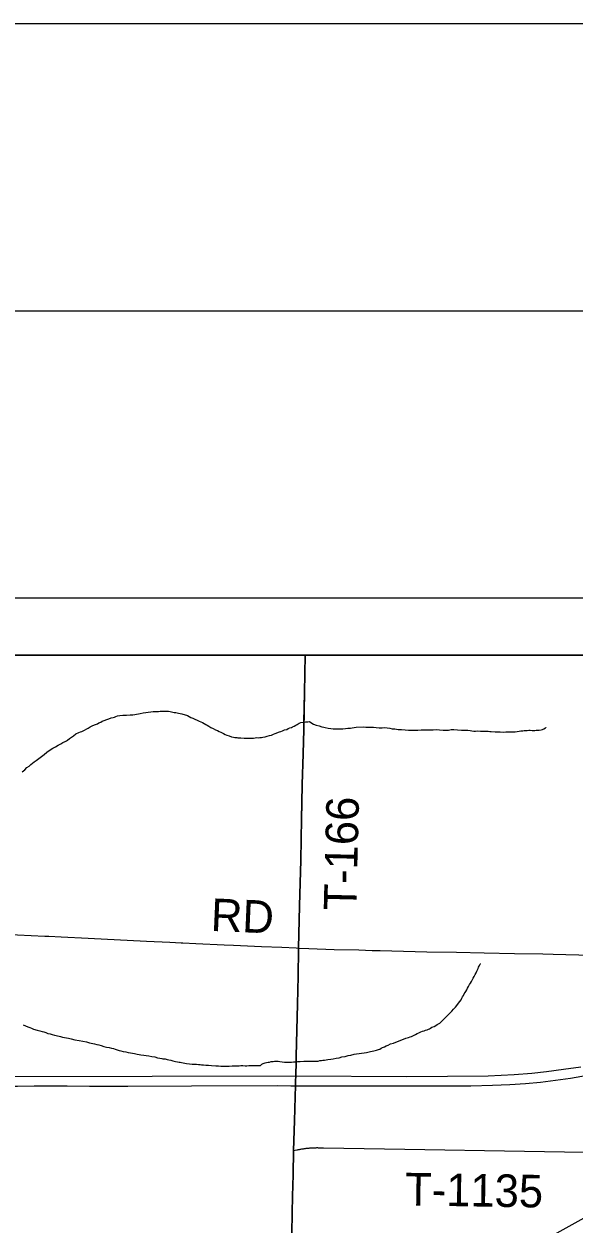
# Model space of a CAD drawing. Extents: x 0 to 34, y 0 to 22.
# Drawn here: x 28.42 to 29.379, y 19.908 to 22 of the extents above; entities that cross this region are included whole.
import ezdxf

# ---------------------------------------------------------------- set-up
doc = ezdxf.new("R2010")
doc.units = 0
for name, color, linetype in [('GM_X_City_Street', 7, 'Continuous'), ('GM_X_County_Road', 7, 'Continuous'), ('GM_X_County_Road_Text', 7, 'Continuous'), ('GM_X_Minor_River', 7, 'Continuous'), ('GM_X_Rail_Line', 7, 'Continuous'), ('GM_X_Township_Road', 7, 'Continuous'), ('GM_X_Township_Road_Text', 7, 'Continuous'), ('GM_X_US_Route', 7, 'Continuous'), ('SH_Border', 7, 'Continuous'), ('SH_Cut_Line', 7, 'Continuous'), ('SH_Data', 7, 'Continuous')]:
    doc.layers.add(name, color=color, linetype=linetype)

msp = doc.modelspace()

# ---------------------------------------------------------------- linework, layer by layer
at = {"layer": 'GM_X_City_Street'}
msp.add_lwpolyline([(28.8904, 20.0361), (28.8959, 20.0373), (28.8971, 20.0376), (28.8983, 20.0379), (28.8995, 20.0381), (28.9007, 20.0384), (28.9019, 20.0386), (28.9032, 20.0388), (28.9044, 20.039), (28.9056, 20.0392), (28.9062, 20.0393), (28.9074, 20.0395), (28.9086, 20.0397), (28.9099, 20.0399), (28.9111, 20.0401), (28.9123, 20.0402), (28.9135, 20.0403), (28.9148, 20.0405), (28.916, 20.0406), (28.9172, 20.0407), (28.9185, 20.0408), (28.9197, 20.0409), (28.9209, 20.041), (28.9222, 20.0411), (28.9228, 20.0411), (28.924, 20.0412), (28.9246, 20.0412), (28.9259, 20.0413), (28.9265, 20.0413), (28.9277, 20.0413), (28.929, 20.0413), (28.9296, 20.0413), (28.9308, 20.0414), (28.932, 20.0414), (28.9333, 20.0413), (28.9339, 20.0413), (28.9351, 20.0413), (28.9364, 20.0413), (28.9376, 20.0412), (28.9382, 20.0412), (28.9395, 20.0412), (28.9401, 20.0411), (28.9413, 20.0411), (28.9425, 20.041), (29.0843, 20.0386), (29.502, 20.0316)], dxfattribs=at)
at = {"layer": 'GM_X_County_Road'}
for points in [[(29.3428, 20.3785), (29.41, 20.3768), (29.4264, 20.3781), (29.4402, 20.3804), (29.4531, 20.3834), (29.4669, 20.3876), (29.4833, 20.3942), (29.4938, 20.4005), (29.5076, 20.409), (29.5198, 20.4179), (29.5323, 20.4291), (29.5454, 20.4432), (29.6523, 20.5721)], [(28.2557, 20.4201), (28.3015, 20.4177), (28.3605, 20.4149), (28.4562, 20.4101), (28.4633, 20.4098)], [(28.4633, 20.4098), (28.4847, 20.4089), (28.5319, 20.4065), (28.6338, 20.4015), (28.6742, 20.3993), (28.694, 20.3983), (28.6971, 20.3982)], [(28.6971, 20.3982), (28.7195, 20.3971), (28.7694, 20.3949)], [(28.7694, 20.3949), (28.7853, 20.3941), (28.8344, 20.3919), (28.8698, 20.3906), (28.8947, 20.3895), (28.8993, 20.3893)], [(28.8993, 20.3893), (28.917, 20.3887), (28.9611, 20.3869), (29.004, 20.3859), (29.0276, 20.3852), (29.0415, 20.3848)], [(29.0415, 20.3848), (29.1227, 20.3829), (29.1743, 20.3818), (29.2228, 20.3809), (29.2757, 20.3798), (29.3248, 20.3789), (29.3428, 20.3785)]]:
    msp.add_lwpolyline(points, dxfattribs=at)
at = {"layer": 'GM_X_Minor_River'}
for points in [[(28.4169, 20.6963), (28.4212, 20.7), (28.4251, 20.7037), (28.429, 20.7062), (28.4321, 20.7092), (28.4348, 20.7114), (28.4379, 20.7136), (28.441, 20.7162), (28.455, 20.7268), (28.4601, 20.7308), (28.4655, 20.7345), (28.4705, 20.7374), (28.4752, 20.7403), (28.4798, 20.7428), (28.484, 20.7453), (28.4879, 20.7475), (28.4918, 20.7493), (28.4941, 20.7507), (28.496, 20.7514), (28.4995, 20.7548), (28.503, 20.7569), (28.5065, 20.7591), (28.5104, 20.7624), (28.5158, 20.7649), (28.5188, 20.7664), (28.5208, 20.7667), (28.5231, 20.7681), (28.5319, 20.7728), (28.5354, 20.7746), (28.5401, 20.7772), (28.5447, 20.7789), (28.5485, 20.7803), (28.5508, 20.7818), (28.5539, 20.7832), (28.5566, 20.7847), (28.5601, 20.7861), (28.5643, 20.7875), (28.5681, 20.7889), (28.572, 20.7903), (28.5754, 20.7913), (28.5777, 20.792)], [(28.5777, 20.792), (28.58, 20.7931), (28.5831, 20.7942), (28.5873, 20.7948), (28.5922, 20.795), (28.5991, 20.7952), (28.6052, 20.7958), (28.6101, 20.796), (28.6132, 20.7963), (28.6162, 20.797), (28.6197, 20.7973), (28.6227, 20.798), (28.6277, 20.799), (28.6323, 20.7996), (28.6368, 20.8002), (28.641, 20.8012), (28.6452, 20.8015), (28.6486, 20.8014), (28.6517, 20.8017), (28.6547, 20.8016), (28.6574, 20.8019), (28.6608, 20.8022), (28.6635, 20.8021), (28.6661, 20.802), (28.6699, 20.8019), (28.6722, 20.8019), (28.6748, 20.8014), (28.6775, 20.8009), (28.6798, 20.8005), (28.682, 20.8001), (28.6847, 20.8), (28.6873, 20.7991), (28.6896, 20.7987), (28.6922, 20.7982), (28.6956, 20.7974), (28.705, 20.7945), (28.708, 20.7928), (28.711, 20.7912), (28.7144, 20.79), (28.7178, 20.788), (28.7219, 20.7864), (28.7256, 20.7847), (28.7286, 20.7835), (28.7316, 20.7823), (28.7343, 20.7807), (28.7372, 20.7791), (28.7395, 20.7775), (28.7425, 20.7759), (28.7458, 20.7739), (28.7499, 20.7719), (28.7541, 20.7699), (28.7578, 20.7682), (28.7604, 20.767), (28.7631, 20.7658), (28.7657, 20.7642), (28.7679, 20.763), (28.7709, 20.7618), (28.7739, 20.7602), (28.7777, 20.7589), (28.7818, 20.7577), (28.7856, 20.7568), (28.7875, 20.7563), (28.7894, 20.7563), (28.7913, 20.7562), (28.7932, 20.7558), (28.7954, 20.7557), (28.7981, 20.7557), (28.8038, 20.7551), (28.8079, 20.755), (28.8129, 20.7549), (28.8167, 20.7551), (28.8201, 20.7554), (28.8232, 20.7557), (28.8258, 20.756), (28.8285, 20.7559), (28.8312, 20.7562), (28.8342, 20.7565), (28.8369, 20.7568), (28.8407, 20.7575), (28.8441, 20.7585), (28.848, 20.7595), (28.8518, 20.7606), (28.8553, 20.762), (28.8583, 20.763), (28.8656, 20.7659), (28.8683, 20.7669), (28.871, 20.768), (28.8745, 20.7694), (28.8787, 20.7704), (28.881, 20.7719), (28.8837, 20.773), (28.8864, 20.774), (28.8883, 20.7747), (28.8914, 20.7762), (28.8941, 20.778), (28.8964, 20.7791), (28.8999, 20.7812), (28.9029, 20.7823), (28.9075, 20.7829), (28.911, 20.7836), (28.9151, 20.7838)], [(28.9151, 20.7838), (28.9182, 20.7841), (28.9204, 20.7822), (28.9249, 20.7798), (28.9298, 20.7777), (28.9351, 20.7764), (28.9396, 20.7751), (28.943, 20.7743), (28.9456, 20.7735), (28.9505, 20.7726), (28.9551, 20.772), (28.9596, 20.7715), (28.9649, 20.7714), (28.9706, 20.7712), (28.9763, 20.7714), (28.9809, 20.7717), (28.9851, 20.7723), (28.9893, 20.7726), (28.9923, 20.7733), (28.9958, 20.7739), (28.9996, 20.7742), (29.0125, 20.7746), (29.0163, 20.7745), (29.0201, 20.7744), (29.0243, 20.7742), (29.0296, 20.7741), (29.0345, 20.7739), (29.0398, 20.7734), (29.0447, 20.7733), (29.0493, 20.7735), (29.0538, 20.773), (29.058, 20.7725), (29.0622, 20.7716), (29.0667, 20.7711), (29.0728, 20.7702), (29.0788, 20.77), (29.0849, 20.7694), (29.0906, 20.7693), (29.0963, 20.7691), (29.1016, 20.769), (29.1069, 20.7688), (29.1126, 20.7694), (29.121, 20.7695), (29.1274, 20.7697), (29.1339, 20.7699), (29.1388, 20.7702), (29.1449, 20.7696), (29.151, 20.7691), (29.1567, 20.7689), (29.1605, 20.7692), (29.1654, 20.7702), (29.1696, 20.77), (29.1761, 20.7695), (29.1829, 20.7693), (29.189, 20.7691), (29.1943, 20.7689), (29.1984, 20.7684), (29.2011, 20.768), (29.2049, 20.7675), (29.2075, 20.7674), (29.2106, 20.7677), (29.2163, 20.7676), (29.2216, 20.7674), (29.2261, 20.7673), (29.2295, 20.7672), (29.2326, 20.7667), (29.2348, 20.7666), (29.242, 20.766), (29.2458, 20.7663), (29.2504, 20.7662), (29.2565, 20.7656), (29.2603, 20.7659), (29.2641, 20.7662), (29.2683, 20.7661), (29.2732, 20.7663), (29.277, 20.7662), (29.2801, 20.7669), (29.2835, 20.7671), (29.2869, 20.7678), (29.29, 20.7681), (29.2926, 20.7684), (29.2953, 20.7683), (29.298, 20.7686), (29.3006, 20.7689), (29.3029, 20.7689), (29.3067, 20.7687), (29.3086, 20.7687), (29.3109, 20.7686), (29.3132, 20.7689), (29.3154, 20.7689), (29.3185, 20.7692), (29.3219, 20.7698), (29.3246, 20.7705), (29.3269, 20.7716), (29.3296, 20.7734), (29.3304, 20.7738), (29.3304, 20.7734)], [(29.0455, 20.2157), (29.0486, 20.2171), (29.0517, 20.2186), (29.0555, 20.22), (29.0594, 20.2221), (29.0647, 20.2235), (29.0686, 20.2253), (29.0732, 20.227), (29.0774, 20.2288), (29.082, 20.2306), (29.0862, 20.232), (29.0905, 20.2334), (29.0935, 20.2344), (29.0958, 20.2351), (29.0981, 20.2362), (29.1004, 20.2373), (29.1028, 20.2384), (29.1059, 20.2402), (29.1089, 20.2416), (29.112, 20.243), (29.1151, 20.2441), (29.1178, 20.2451), (29.1205, 20.2462), (29.1231, 20.2469), (29.1255, 20.248), (29.1274, 20.2487), (29.1293, 20.2498), (29.1316, 20.2512), (29.1355, 20.2526), (29.1382, 20.2541), (29.1409, 20.2559), (29.1432, 20.257), (29.1451, 20.2584), (29.1482, 20.261), (29.1502, 20.2628), (29.1522, 20.2651), (29.1549, 20.2676), (29.158, 20.271), (29.1627, 20.2758), (29.1663, 20.2795), (29.1694, 20.2828), (29.1725, 20.2865), (29.1804, 20.2962), (29.1824, 20.2991), (29.1836, 20.3018), (29.1852, 20.3044), (29.1864, 20.3066), (29.188, 20.3096), (29.1896, 20.3115), (29.1908, 20.3137), (29.1924, 20.3163), (29.1936, 20.3193), (29.1952, 20.3223), (29.1972, 20.3257), (29.1988, 20.3283), (29.2004, 20.3309), (29.202, 20.3335), (29.2036, 20.3365), (29.2052, 20.3395), (29.2069, 20.3433), (29.2085, 20.3463), (29.2097, 20.3489), (29.2109, 20.3512), (29.2121, 20.3538), (29.2129, 20.356), (29.2138, 20.3579), (29.2154, 20.3605), (29.2162, 20.362), (29.2158, 20.362)], [(28.4184, 20.2554), (28.4225, 20.2534), (28.4266, 20.2518), (28.4304, 20.2509), (28.433, 20.2497), (28.4368, 20.2477), (28.4428, 20.2464), (28.4477, 20.2451), (28.4515, 20.2439), (28.4549, 20.243), (28.4583, 20.2418), (28.4616, 20.2405), (28.4654, 20.2397), (28.4692, 20.2384), (28.473, 20.2375), (28.476, 20.2367), (28.4786, 20.2362), (28.4816, 20.2358), (28.4839, 20.2349), (28.4869, 20.2341), (28.4975, 20.2319), (28.5024, 20.231), (28.5088, 20.2293), (28.516, 20.2279), (28.5228, 20.227), (28.5288, 20.2257), (28.5345, 20.224), (28.5401, 20.2231), (28.5428, 20.2222), (28.5469, 20.2213), (28.5507, 20.2205), (28.5548, 20.2192), (28.5594, 20.2179), (28.5639, 20.2167), (28.5688, 20.2158), (28.5729, 20.2149), (28.5763, 20.214), (28.579, 20.2132), (28.5827, 20.2119), (28.5861, 20.2107), (28.5891, 20.2099), (28.5929, 20.209), (28.5974, 20.2081), (28.602, 20.2072), (28.6058, 20.2067), (28.6092, 20.2062), (28.6129, 20.2054), (28.6175, 20.2045), (28.6209, 20.204), (28.6239, 20.2032), (28.6288, 20.2026), (28.633, 20.2018)], [(28.633, 20.2018), (28.6375, 20.2012), (28.6428, 20.2003), (28.6481, 20.1994), (28.653, 20.1981), (28.6571, 20.1976), (28.6602, 20.1968), (28.662, 20.1964), (28.6639, 20.1963), (28.6662, 20.1959), (28.6696, 20.195), (28.6726, 20.1945), (28.676, 20.1937), (28.6798, 20.1924), (28.6843, 20.1915), (28.6877, 20.1911), (28.6907, 20.1906), (28.6926, 20.1902), (28.6945, 20.1897), (28.7032, 20.1879), (28.7085, 20.1874), (28.7134, 20.1869), (28.718, 20.1868), (28.721, 20.1867), (28.7244, 20.1862), (28.7275, 20.1861), (28.7297, 20.1857), (28.7331, 20.1856), (28.7373, 20.1851), (28.7419, 20.1849), (28.7472, 20.1844), (28.7544, 20.1842), (28.7593, 20.1837), (28.7635, 20.1835), (28.7673, 20.1834), (28.7718, 20.1833), (28.7779, 20.1835), (28.7832, 20.1837), (28.7874, 20.184), (28.7916, 20.1839), (28.7954, 20.1841), (28.7984, 20.1844), (28.8015, 20.1843), (28.8057, 20.1842), (28.8087, 20.1841), (28.8121, 20.1844), (28.8167, 20.1847), (28.8228, 20.1845), (28.8277, 20.1844), (28.8304, 20.1847), (28.8326, 20.1846), (28.8346, 20.1868), (28.8373, 20.1879), (28.8407, 20.1889), (28.843, 20.1896), (28.8457, 20.1903), (28.848, 20.1906), (28.8514, 20.1913), (28.8545, 20.1916), (28.8572, 20.1919), (28.8591, 20.1922), (28.8632, 20.1921), (28.8663, 20.1916), (28.8701, 20.1911), (28.8742, 20.1906), (28.8788, 20.1901), (28.8829, 20.1904), (28.8867, 20.1906), (28.8902, 20.1909), (28.8932, 20.1912), (28.897, 20.1915), (28.9016, 20.1917), (28.9084, 20.1919), (28.9138, 20.1921), (28.9198, 20.192), (28.9255, 20.1922), (28.9301, 20.192), (28.9331, 20.1923), (28.9362, 20.193), (28.9389, 20.1933), (28.9415, 20.1936), (28.9442, 20.1939), (28.9469, 20.1942), (28.9503, 20.1949), (28.9553, 20.1955), (28.9595, 20.1961), (28.9648, 20.1971), (28.9698, 20.1981), (28.9744, 20.1995), (28.9801, 20.2005), (28.9855, 20.2018), (28.9904, 20.2028), (28.9958, 20.2042), (29.0175, 20.2074), (29.0244, 20.2087), (29.0301, 20.21), (29.0347, 20.2111), (29.0382, 20.2125), (29.0405, 20.2132), (29.0428, 20.2146), (29.0455, 20.2157)]]:
    msp.add_lwpolyline(points, dxfattribs=at)
at = {"layer": 'GM_X_Rail_Line'}
msp.add_lwpolyline([(29.1835, 19.8007), (29.9023, 20.1997)], dxfattribs=at)
at = {"layer": 'GM_X_Township_Road'}
for p, q in [((28.9104, 20.8873), (28.9106, 20.9)), ((28.9082, 20.7747), (28.9084, 20.7837)), ((28.8973, 20.2911), (28.8977, 20.3109))]:
    msp.add_line(p, q, dxfattribs=at)
for points in [[(28.887, 19.8915), (28.8877, 19.9276), (28.8884, 19.9568), (28.8895, 19.9942), (28.8902, 20.0366), (28.8916, 20.0879), (28.893, 20.1302), (28.8935, 20.1497), (28.8937, 20.1571), (28.894, 20.1668), (28.8946, 20.1915), (28.8949, 20.2008), (28.8952, 20.2232), (28.8965, 20.2686), (28.8971, 20.2916), (28.898, 20.3401), (28.8989, 20.3865), (28.899, 20.3899), (28.9007, 20.4627), (28.9028, 20.5422), (28.9041, 20.6143), (28.9049, 20.6429), (28.9055, 20.6746), (28.9069, 20.728), (28.9079, 20.7703), (28.9091, 20.8349), (28.9104, 20.9), (23.5167, 20.9)], [(30.3167, 20.9), (28.9104, 20.9), (28.9091, 20.8349), (28.9079, 20.7703), (28.9069, 20.728), (28.9055, 20.6746), (28.9049, 20.6429), (28.9041, 20.6143), (28.9028, 20.5422), (28.9007, 20.4627), (28.899, 20.3899), (28.8989, 20.3865), (28.898, 20.3401), (28.8971, 20.2916), (28.8965, 20.2686), (28.8952, 20.2232), (28.8949, 20.2008), (28.8946, 20.1915), (28.894, 20.1668), (28.8937, 20.1571), (28.8935, 20.1497), (28.893, 20.1302), (28.8916, 20.0879), (28.8902, 20.0366), (28.8895, 19.9942), (28.8884, 19.9568), (28.8877, 19.9276), (28.887, 19.8915)], [(28.9084, 20.7837), (28.9093, 20.8344), (28.9104, 20.8873)], [(28.8993, 20.3893), (28.901, 20.4621), (28.903, 20.5417), (28.9044, 20.6138), (28.9052, 20.6423), (28.9058, 20.6741), (28.9072, 20.7275), (28.9081, 20.7698), (28.9082, 20.7747)], [(28.8977, 20.3109), (28.8982, 20.3395), (28.8992, 20.3859), (28.8993, 20.3893)], [(28.8938, 20.1491), (28.894, 20.1565), (28.8942, 20.1663), (28.8948, 20.1909), (28.8951, 20.2002), (28.8955, 20.2226), (28.8967, 20.2681), (28.8973, 20.2911)], [(28.8904, 20.0361), (28.8918, 20.0874), (28.8932, 20.1296), (28.8938, 20.1491)], [(28.8823, 19.6941), (28.8823, 19.6952), (28.883, 19.7157), (28.8835, 19.7399), (28.8842, 19.7642), (28.885, 19.8002), (28.8853, 19.8238), (28.886, 19.8487), (28.8868, 19.8761), (28.8872, 19.891), (28.8879, 19.927), (28.8887, 19.9562), (28.8897, 19.9936), (28.8904, 20.0361)]]:
    msp.add_lwpolyline(points, dxfattribs=at)
at = {"layer": 'GM_X_US_Route'}
for points in [[(29.0865, 20.149), (29.0875, 20.149), (29.1993, 20.1493), (29.2371, 20.1501), (29.2676, 20.1514), (29.2948, 20.1532), (29.3208, 20.1557), (29.3473, 20.1589), (29.3731, 20.1627), (29.4031, 20.1679), (29.4305, 20.1734), (29.4614, 20.1804), (29.4891, 20.1874), (29.5035, 20.1912), (29.5044, 20.1915)], [(28.393, 20.1652), (28.8942, 20.1663), (29.0877, 20.1653), (29.2299, 20.1663), (29.2752, 20.1687), (29.3061, 20.1713), (29.3314, 20.1739), (29.361, 20.1779), (29.3916, 20.1825)], [(28.3922, 20.1488), (28.3932, 20.1488), (28.4085, 20.1488), (28.4377, 20.149), (28.4955, 20.1493), (28.5345, 20.1488), (28.6014, 20.1488), (28.712, 20.1491), (28.8624, 20.1494), (28.8856, 20.1492), (28.8938, 20.1491)], [(28.8938, 20.1491), (29.0389, 20.1493), (29.0865, 20.149)]]:
    msp.add_lwpolyline(points, dxfattribs=at)
at = {"layer": 'SH_Border'}
msp.add_lwpolyline([(1.5, 21.5), (33.5, 21.5), (33.5, 0.5), (1.5, 0.5)], close=True, dxfattribs=at)
at = {"layer": 'SH_Cut_Line'}
msp.add_lwpolyline([(0, 0), (34, 0), (34, 22), (0, 22)], close=True, dxfattribs=at)
at = {"layer": 'SH_Data'}
for points in [[(23.4167, 21), (30.4167, 21), (30.4167, 14), (23.4167, 14)], [(23.5167, 20.9), (30.3167, 20.9), (30.3167, 14.1), (23.5167, 14.1)]]:
    msp.add_lwpolyline(points, close=True, dxfattribs=at)

# ---------------------------------------------------------------- texts
at = {"layer": 'GM_X_County_Road_Text'}
msp.add_text('RD', height=0.05682, rotation=357.554, dxfattribs=at).set_placement((28.7451, 20.4192))
at = {"layer": 'GM_X_Township_Road_Text'}
for s, rotation, p in [('T-166', 88.5955, (28.9996, 20.4541)), ('T-1135', 359.0643, (29.0844, 19.9408))]:
    msp.add_text(s, height=0.05682, rotation=rotation, dxfattribs=at).set_placement(p)

doc.saveas('drawing.dxf')
